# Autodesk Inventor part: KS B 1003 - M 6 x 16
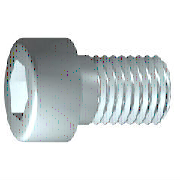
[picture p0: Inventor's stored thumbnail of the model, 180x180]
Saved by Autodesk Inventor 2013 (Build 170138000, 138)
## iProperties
Created: 2009-02
Part Number: KS B 1003 - M 6 x 16
Material: Steel, Mild
Description: 6각머리 태핑 나사
Document SubType Name: Modeling
Standard: KS B 1003
Designer: KYOUNG IL JANG
Standards Organization: KS
Language: ko-KR
Size Designation: M 6 x 16
Categories: <MemberInstance><Categories><Category DisplayName="조임쇠" InternalName="e4da775c-781d-43d5-af7c-5136215cf5a6" Mnemonic="FSTN"><Category DisplayName="볼트" InternalN
Density: 1 g/cm^3
Company: 한국ATC센터
IsCustomPart: 0
Author: KYOUNG IL JANG
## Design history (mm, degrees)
sketch "스케치1"
  geometry: L1 (-1.333, 0)-(16, 0); L2 (16, 0)-(16, 3); L3 (16, 3)-(2.5, 3); L4 (2.5, 3)-(1.886, 3); L5 (1.886, 3)-(0, 3); L6 (0, 3)-(0, 5); L7 (0, 5)-(-6, 5); L8 (-6, 5)-(-6, 2.887); L9 (-6, 2.887)-(-3, 2.887); L10 (-3, 2.887)-(-1.333, 0); L11 (-10.4, 0)-(20.4, 0) reference; L12 (0, -1)-(0, 6) reference; L13 (2.5, 3)-(0, 3)
  constraints: 22 end point, 6 parallel, 2 collinear, 2 perpendicular, 1 horizontal, 1 point on line
  dimensions: "d1" = 13.5 distance from line of L3.end L2 (= GEL); "d2" = 0.61355 distance of L4.end L3.end (computed from GAL); "d3" = 6 distance between parallel lines of L8 L6 (= KOH); "d4" = 3 distance of L8.end L9.end (= INTI); "d5" = 60 deg angle of L10 L1; "d6" = 6 diameter of L3 L1 (= GD); "d7" = 6 diameter of L5 L1 (= BDM); "d8" = 5.7735 diameter of L9 L1 (= 1.1547 x SW); "d9" = 10 diameter of L7 L1 (= KOD); "d26" = 16 distance between parallel lines of L12 L2 (= NLG)
revolve "본체" sketch "스케치1" stored, may be unused: angle "d10" = 90 deg
sketch "스케치2"
  geometry: L1 (0, -7)-(0, 7) reference; L2 (-7, 0)-(7, 0) reference; L3 (2.887, 0)-(1.443, -2.5); L4 (1.443, -2.5)-(-1.443, -2.5); L5 (-1.443, -2.5)-(-2.887, 0); L6 (-2.887, 0)-(-1.443, 2.5); L7 (-1.443, 2.5)-(1.443, 2.5); L8 (1.443, 2.5)-(2.887, 0); 2 further points
  constraints: 12 end point, 1 coincident, 1 horizontal alignment, 1 point on line, 12 other
extrude "슬롯" join sketch "스케치2" stored distance "d11" = 10; taper "d12" = 0 deg
workplane "Work Plane1"
fillet "Fillet2" dims "d30" = 0.1 (= R)
body "Solid1"
fillet "모깎기1" dims "d17" = 0.6 (= RR)
feature "스레드" dims "d13" = 13.5 (= GEL), "d14" = 0
chamfer "모따기1" distance "d15" = 0.61345 (= -0.5 x SPD + 0.5 x GD); stored, may be unused: second distance "d16" = 0.61345 (= GUL), angle "d27" = 45 deg
other parameters: "GD" = 6 (= NND) [user parameter; used in 2 equation terms], "NLG" = 16 [user parameter; used in 1 equation term], "GEL" = 13.5 [user parameter; used in 2 equation terms], "KOD" = 10 [user parameter; used in 1 equation term], "KOH" = 6 [user parameter; used in 1 equation term], "INTI" = 3 [user parameter; used in 1 equation term], "GAL" = 0.61345 (= 0.61345 x PTC) [user parameter; used in 1 equation term], "GUL" = 0.61345 (= 0.61345 x PTC) [user parameter; used in 1 equation term], "BDM" = 6 (= NND) [user parameter; used in 1 equation term], "SW" = 5 [user parameter; used in 2 equation terms], "RR" = 0.6 [user parameter; used in 1 equation term], "SPD" = 4.7731 (= NND - 1.2269 x PTC) [user parameter; used in 1 equation term], "d19" = 0, "d28" = 0, "d29" = 0, "R" = 0.1 [user parameter; used in 1 equation term], "PHH" = 0.25 [user parameter], "GD1" = 4.7731 (= THREADDIA - 1.2269 x PTC) [user parameter], "THREADDIA" = 6 [user parameter; used in 1 equation term], "FAWI" = 45 deg [user parameter], "PTC" = 1 [user parameter; used in 5 equation terms], "NND" = 6 [user parameter; used in 3 equation terms], "TOA" = 30 deg [user parameter], "E0" = 5.775 (= 1.155 x SW) [user parameter]
